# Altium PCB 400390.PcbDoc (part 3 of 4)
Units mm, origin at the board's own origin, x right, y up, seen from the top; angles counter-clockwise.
Board outline 50.8 x 50.4 mm, 4 copper layers (Top Layer, Mid Layer 1, Mid Layer 2, Bottom Layer), stack 1.507 mm thick; 236 components, 197 nets, 1131 pads, 994 vias.
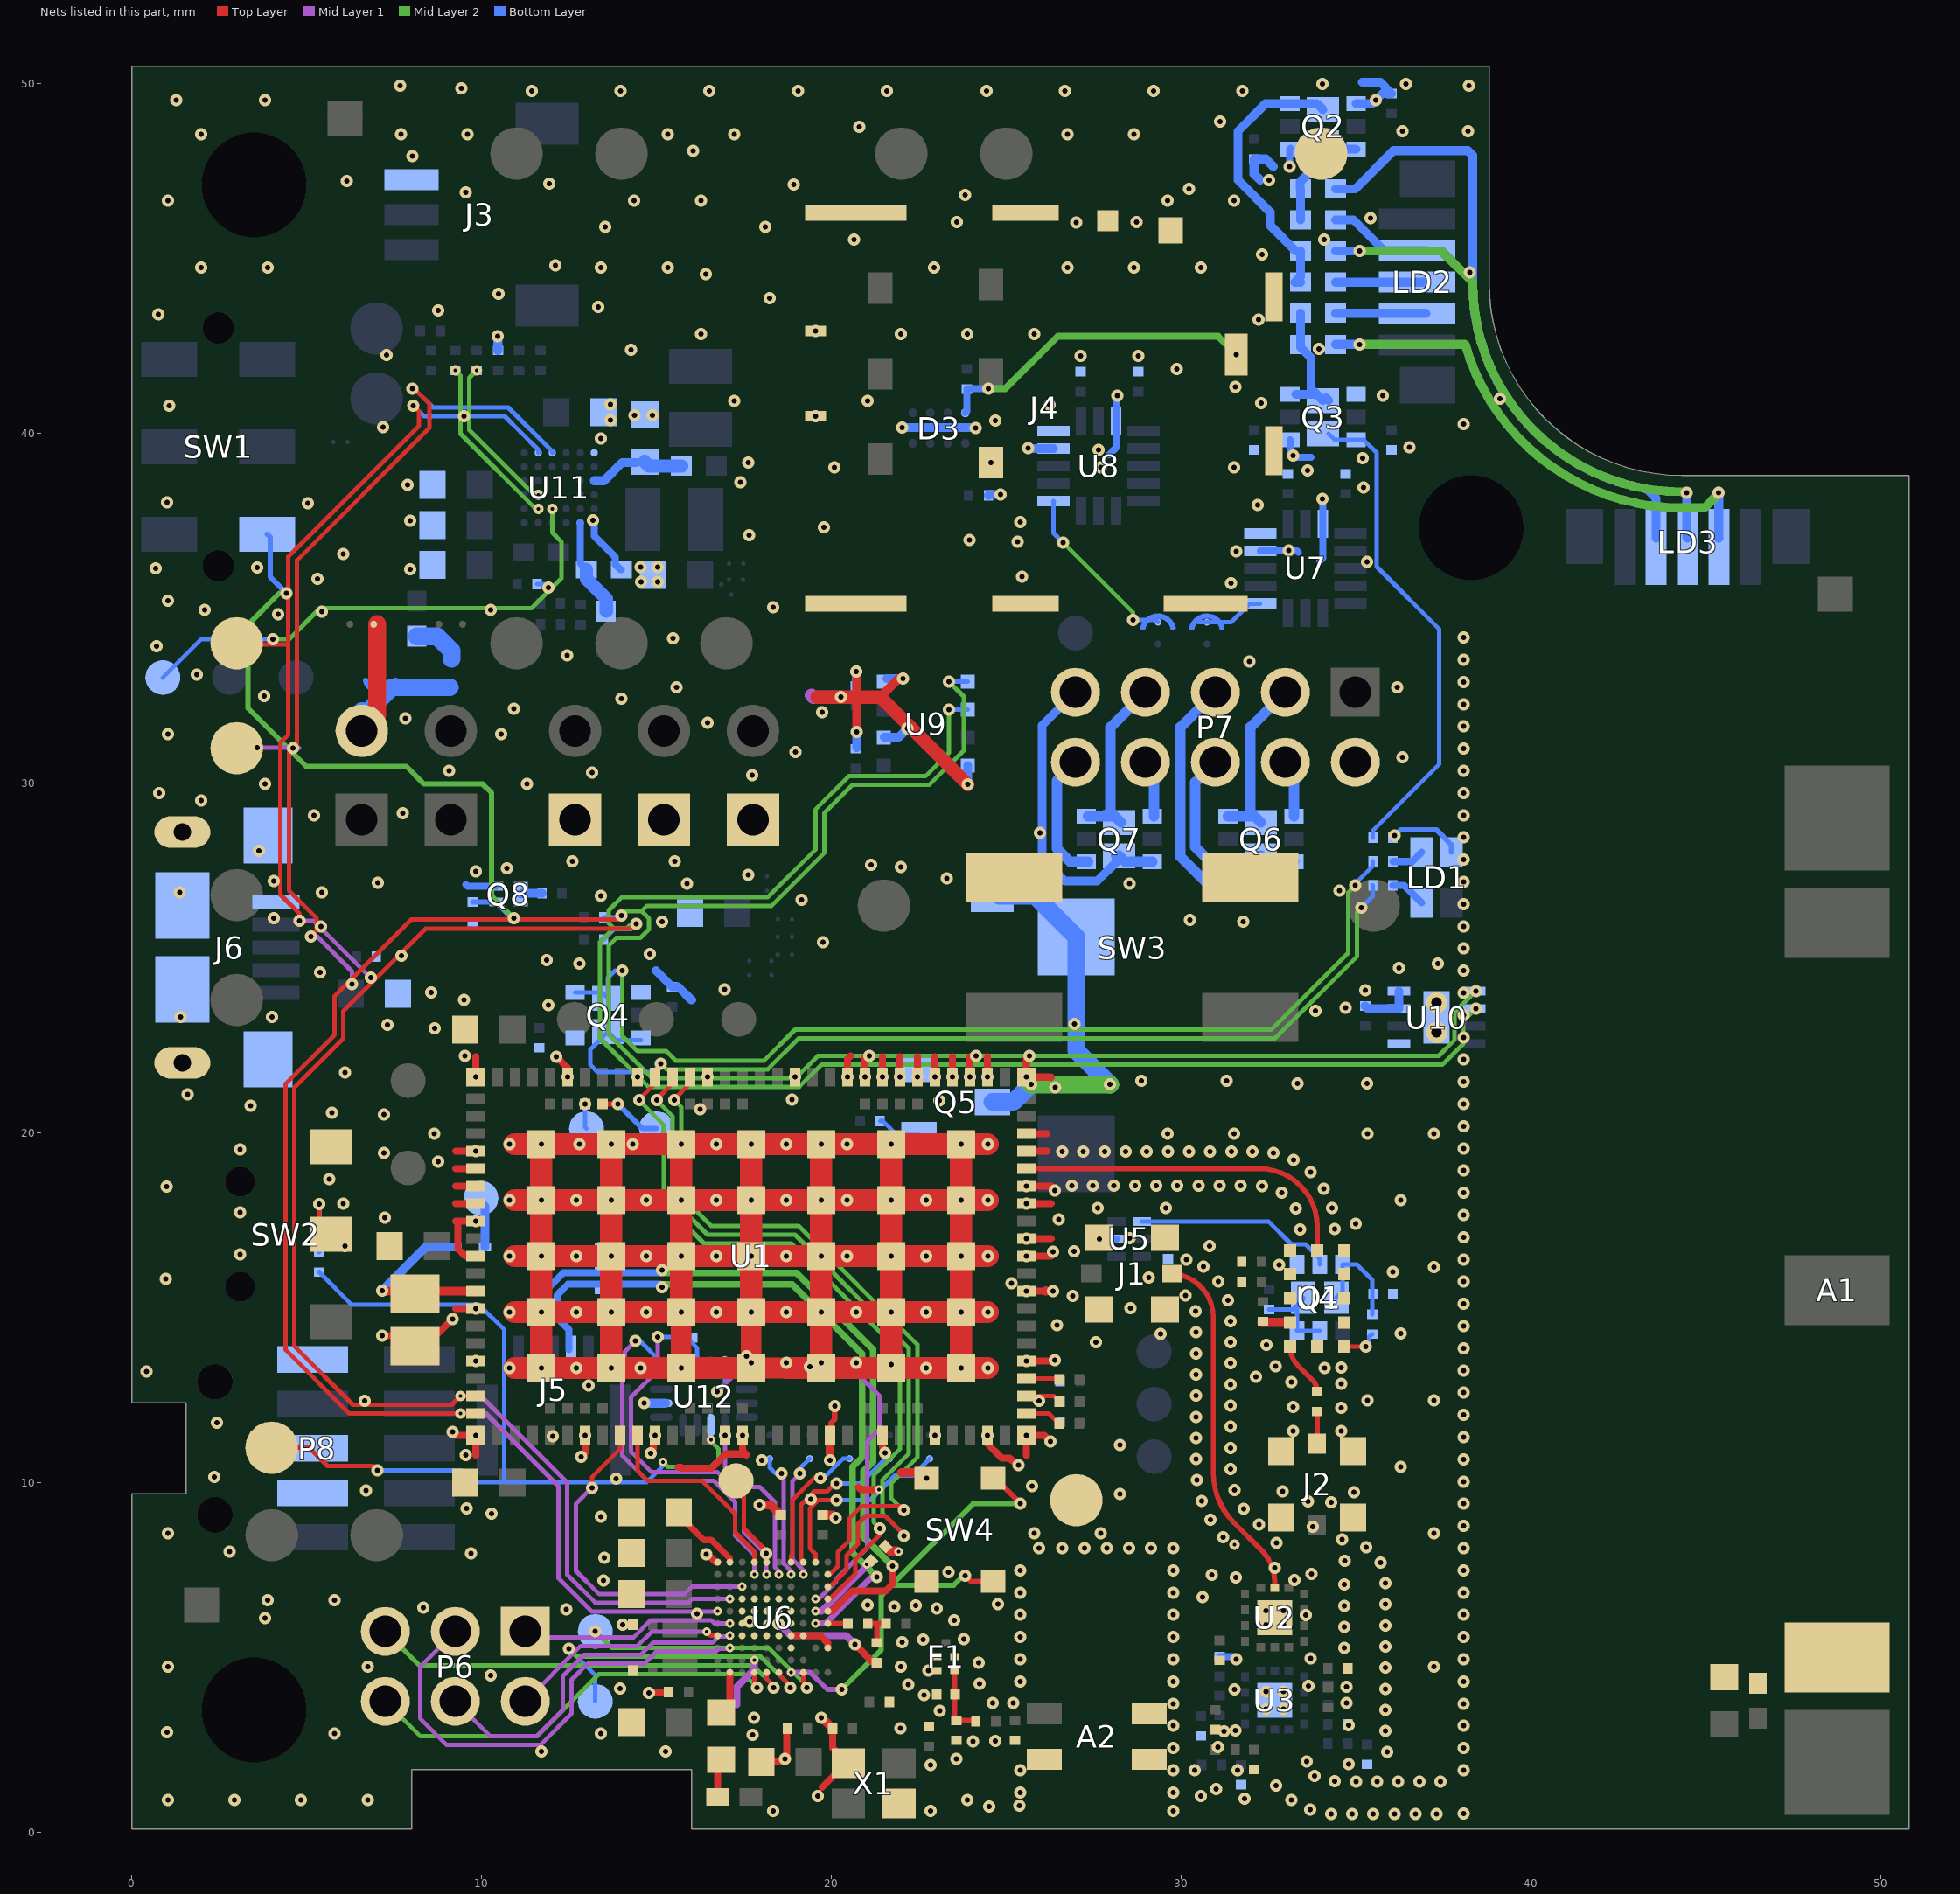
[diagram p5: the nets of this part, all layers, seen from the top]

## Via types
v1: diameter 0.35, hole 0.15, Top Layer to Bottom Layer, tented both sides, 565 vias
v2: diameter 0.35, hole 0.15, Top Layer to Mid Layer 1, tented both sides, 201 vias
v3: diameter 0.35, hole 0.15, Mid Layer 2 to Bottom Layer, tented both sides, 153 vias
v4: diameter 0.25, hole 0.1, Top Layer to Mid Layer 1, tented both sides, 35 vias
v5: diameter 0.3, hole 0.1, Mid Layer 2 to Bottom Layer, tented both sides, 26 vias
v6: diameter 0.25, hole 0.1, Mid Layer 2 to Bottom Layer, tented both sides, 5 vias
v7: diameter 0.35, hole 0.15, Top Layer to Mid Layer 1, 4 vias
v8: diameter 0.3, hole 0.1, Top Layer to Mid Layer 1, tented both sides, 3 vias
v9: diameter 0.61, hole 0.305, Top Layer to Bottom Layer, tented both sides, 2 vias

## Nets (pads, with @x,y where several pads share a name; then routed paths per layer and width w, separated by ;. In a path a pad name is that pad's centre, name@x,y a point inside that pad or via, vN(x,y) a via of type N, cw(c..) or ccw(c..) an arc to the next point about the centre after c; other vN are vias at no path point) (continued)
GND: A2.2 C1.1 C2.1 C3.2 C4.2 C5.1 C6.1 C7.1 C8.1 C12.1 C13.1 C14.1 C16.1 C17.1 C18.2 C19.2 C20.1 C21.2 C22.2 C23.2 C24.2 C25.2 C26.2 C27.2 C28.1 C29.2 C30.2 C31.2 C32.2 C33.2 C35.2 C36.1 C37.1 C38.1 C39.1 C40.1 C41.1 C42.1 C43.2 C44.2 C45.1 C46.1 C47.1 C48.1 C49.1 C50.1 C51.1 C53.1 C54.2 C55.2 C56.2 C57.1 CR1.1 D3.B1 D3.B2 F1.2 F1.3 F1.5 J1.2 J2.2 J3.1 J4.0 J4.C5 J4.CSW J6.5 J6.6@1.45,22 J6.6@1.45,24.1 J6.6@1.45,26.5 J6.6@1.45,28.6 J6.6@3.9,22.1 J6.6@3.9,28.5 L4.1 L5.1 L6.1 L7.1 L15.2 P3.1 P4.1 P5.1 P7.2 P8.3 P8.5 P8.9 Q1.1 Q2.1 Q2.4 Q3.1 Q3.4 Q4.1 Q4.4 Q5.2 Q8.2 R4.1 R5.1 R6.1 R32.1 R40.2 R41.1 R42.1 R43.1 R44.1 R45.1 R46.1 R48.2 ST11.2 SW2.1 SW3.1 SW4.1 TP15.1 TP16.1 U1.1 U1.5 U1.6 U1.7 U1.8 U1.9 U1.11 U1.14 U1.17 U1.21 U1.27 U1.31 U1.36 U1.41 U1.44 U1.47 U1.50 U1.52 U1.56 U1.60 U1.62 U1.63 U1.65 U1.66 U1.68 U1.69 U1.72 U1.74 U1.75 U1.76 U1.77 U1.78 U1.79 U1.80 U1.81 U1.82 U1.85 U1.90 U1.94 U1.98 U1.103 U2.15 U3.15 U4.2 U4.4 U4.5 U4.6 U4.7 U4.9 U4.10 U4.11 U5.2 U6.B7 U6.C1 U6.C4 U6.D3 U6.D4 U6.D5 U6.D6 U6.D7 U6.D8 U6.E4 U6.E5 U6.E6 U6.E7 U6.E8 U6.F4 U6.F5 U6.F6 U6.F7 U6.F8 U6.G4 U6.G5 U6.G6 U6.G7 U6.G8 U6.K10 U7.12 U7.13 U7.16 U8.12 U8.13 U8.16 U9.1 U9.5 U9.7 U10.1 U10.3 U10.4 U10.9 U11.A1 U11.F1 U12.6 X1.2 X1.4 | length 187.5
  Top Layer w0.152: U1.41@19.956,11.357 19.98,11.381 19.98,11.701 20.091,11.812 v1(20.091,12.192)
  Top Layer w0.2: v1(7.163,14.199) C3.2@7.744,14.199 ; C3.2@8.522,14.034 v1(9.169,14.681) ; v2@9.255,11.357 v2(9.836,11.357) 9.836,10.776 ; 9.255,14.977 v2(9.836,14.977) ; 9.255,17.977 U1.8@9.836,17.977 ; 9.255,18.477 U1.7@9.836,18.477 ; 9.255,18.977 U1.6@9.836,18.977 ; 9.255,19.477 v2(9.836,19.477) ; U1.11@9.836,16.477 9.533,16.477 9.327,16.683 9.327,17.405 9.255,17.477 v2(9.836,17.477) ; v2(9.836,21.597) 9.836,22.178 ; v1(12.141,22.174) 12.456,21.859 v2(12.456,21.597) ; v1(12.852,10.744) 12.956,10.848 v2(12.956,11.357) ; v1@14.732,3.988 15.315,3.988 C21.2@15.345,4.017 ; C28.1@17.927,1.985 C28.1@18.054,1.858 ; C28.1@18.003,2.011 18.038,2.046 18.561,2.046 18.729,2.214 C29.2@18.729,2.975 ; U6.D4@18.847,5.626 19.635,5.626 19.638,5.622 19.692,5.622 19.897,5.417 U6.C1@19.897,5.276 ; 19.736,1.295 19.739,1.295 20.091,1.647 20.159,1.647 X1.2@20.484,1.972 20.434,1.972 20.109,2.297 20.109,2.347 20.035,2.421 C19.2@20.035,2.97 ; v2(20.456,21.597) 20.456,22.11 20.549,22.203 ; v1(20.669,5.382) 21.198,4.853 C20.1@21.301,4.853 ; v2(20.956,21.597) v7@20.956,22.178 ; v2(21.456,21.597) 21.456,22.178 ; v2(21.956,21.597) 21.956,22.178 ; v2(22.456,21.597) 22.456,22.178 ; v2(22.956,21.597) 22.956,22.178 ; v2(23.456,21.597) 23.456,22.178 ; v2(23.956,21.597) 23.956,22.178 ; v2(24.456,11.357) 24.456,11.119 24.581,10.994 24.713,10.862 24.875,10.7 25.1,10.7 25.175,10.625 ; v2(24.456,21.597) 24.456,22.178 ; 25.576,10.776 v2(25.576,11.357) 26.083,11.357 v1(26.264,11.176) ; U1.68@25.576,19.477 26.157,19.477 ; U1.69@25.576,19.977 26.157,19.977 ; v2(25.576,21.597) v7@25.576,22.178
  Top Layer w0.203: v1(14.834,10.846) 14.834,10.886 14.908,10.96 14.908,11.309 v2(14.956,11.357) ; 15.621,10.439 15.698,10.439 15.719,10.419 16.572,10.419 16.974,10.82 17.551,10.82 ; v1@16.417,8.005 16.696,7.726 U6.K10@16.747,7.726 ; U1.36@17.456,11.357 v2(17.458,11.355) 17.458,10.914 17.551,10.82 ; 17.577,10.795 17.551,10.82 ; 20.774,9.881 20.85,9.804 v4(21.361,9.804) ; 21.456,11.008 U1.44@21.456,11.357 ; v2(25.576,13.477) v1@26.28,13.477 ; v2(25.576,15.477) 26.13,15.477 v2@26.28,15.477 ; v2(25.576,16.477) v2@26.28,16.477 ; v2(25.576,16.977) 26.28,16.977 ; v2(25.576,17.977) 26.28,17.977 ; v2(25.576,18.477) v2@26.28,18.477 ; v2(25.576,21.597) 26.28,21.597
  Top Layer w0.254: v2(9.169,11.455) v2@9.188,11.437 ; v1(17.949,9.367) 18.261,9.367 C23.2@18.55,9.078 ; v1(19.71,3.277) 19.728,3.277 C19.2@20.035,2.97 ; C24.2@19.745,9.078 20.031,9.078 v1(20.117,8.992) ; 19.956,10.837 U1.41@19.956,11.357 ; v1(20.727,31.465) 20.727,32.309 ; 20.727,32.461 v1@20.727,33.242 ; 21.394,32.461 21.903,32.97 22.03,32.97 v1(22.048,32.988) ; C25.2@21.558,8.175 C25.2@21.547,8.175 21.675,8.047 v4@21.855,8.047 ; 21.996,10.287 22.565,10.287 v2(22.723,10.129) ; 26.13,15.477 26.139,15.486
  Top Layer w0.381: 19.583,32.461 v1(20.269,32.461) 20.727,32.461 21.394,32.461 v1(23.895,29.96)
  Top Layer w0.508: v2(13.706,19.677) U1.103@13.824,19.677 ; v2(15.706,19.677) U1.103@15.706,19.712
  Top Layer w0.584: v2(15.706,13.277) v2(15.706,14.877) ; U1.103@17.706,13.277 v2(17.706,14.877)
  Top Layer w0.597: U1.103@17.706,13.277 v2@18.706,13.277
  Top Layer w0.635: v2@10.944,13.277 v2(11.706,13.277) ; v1@10.944,14.877 v2(11.706,14.877) ; v1@10.944,16.477 v2(11.706,16.477) ; v1@10.944,18.077 v2(11.706,18.077) ; v1@10.944,19.677 v2(11.706,19.677) ; U1.103@17.706,13.277 v2(15.706,13.277) v2(13.706,13.277) ; v2@18.706,13.277 U1.103@19.706,13.277 ; v1(24.468,13.277) v2(23.706,13.277) ; v2(24.468,14.877) v2(23.706,14.877) ; v2(24.468,16.477) v2(23.706,16.477) ; v1(24.468,18.077) v2(23.706,18.077) ; v1(24.468,19.677) v2(23.706,19.677) ; v2(11.706,13.277) v2(12.706,13.277) v2(13.706,13.277) ; v2(11.706,13.277) v2(11.706,14.877) ; v2(11.706,14.877) v1(12.706,14.877) v2(13.706,14.877) ; v2(11.706,14.877) v2(11.706,16.477) ; v2(11.706,16.477) v1(12.706,16.477) v2(13.706,16.477) ; v2(11.706,16.477) v2(11.706,18.077) ; v2(11.706,18.077) v1(12.706,18.077) v2(13.706,18.077) ; v2(11.706,18.077) v2(11.706,19.677) ; v2(11.706,19.677) v2(13.706,19.677) ; v2(13.706,13.277) v2(13.706,14.877) ; v2(13.706,14.877) v1(14.706,14.877) v2(15.706,14.877) ; v2(13.706,14.877) v2(13.706,16.477) ; v2(13.706,16.477) v1(14.706,16.477) v2(15.706,16.477) ; v2(13.706,16.477) v2(13.706,18.077) ; v2(13.706,18.077) v1(14.706,18.077) v2(15.706,18.077) ; v2(13.706,18.077) v2(13.706,19.677) ; v2(13.706,19.677) v2(15.706,19.677) ; v2(15.706,14.877) v1(16.706,14.877) v2(17.706,14.877) ; v2(15.706,14.877) v2(15.706,16.477) ; v2(15.706,16.477) v1(16.706,16.477) v2(17.706,16.477) ; v2(15.706,16.477) v2(15.706,18.077) ; v2(15.706,18.077) v1(16.706,18.077) v2(17.706,18.077) ; v2(15.706,18.077) v2(15.706,19.677) ; v2(15.706,19.677) v1(16.706,19.677) v2(17.706,19.677) ; v2(17.706,14.877) v1(18.706,14.877) v2(19.706,14.877) ; v2(17.706,14.877) v2(17.706,16.477) ; v2(17.706,16.477) v1(18.706,16.477) v2(19.706,16.477) ; v2(17.706,16.477) v2(17.706,18.077) ; v2(17.706,18.077) v1(18.706,18.077) v2(19.706,18.077) ; v2(17.706,18.077) v2(17.706,19.677) ; v2(17.706,19.677) v2(18.706,19.677) v2(19.706,19.677) ; U1.103@19.706,13.277 U1.103@21.706,13.277 ; U1.103@19.706,13.277 v2(19.706,14.877) ; v2(19.706,14.877) v2(20.706,14.877) v2(21.706,14.877) ; v2(19.706,14.877) v2(19.706,16.477) ; v2(19.706,16.477) v1(20.452,16.477) v2(21.706,16.477) ; v2(19.706,16.477) v2(19.706,18.077) ; v2(19.706,18.077) v1(20.452,18.077) v2(21.706,18.077) ; v2(19.706,18.077) v2(19.706,19.677) ; v2(19.706,19.677) v1(20.452,19.677) v2(21.706,19.677) ; U1.103@21.706,13.277 v2(22.706,13.277) v2(23.706,13.277) ; U1.103@21.706,13.277 v2(21.706,14.877) ; v2(21.706,14.877) v2(22.706,14.877) v2(23.706,14.877) ; v2(21.706,14.877) v2(21.706,16.477) ; v2(21.706,16.477) v2(22.706,16.477) v2(23.706,16.477) ; v2(21.706,16.477) v2(21.706,18.077) ; v2(21.706,18.077) v1(22.706,18.077) v2(23.706,18.077) ; v2(21.706,18.077) v2(21.706,19.677) ; v2(21.706,19.677) v2(23.706,19.677) ; v2(23.706,13.277) v2(23.706,14.877) ; v2(23.706,14.877) v2(23.706,16.477) ; v2(23.706,16.477) v2(23.706,18.077) ; v2(23.706,18.077) v2(23.706,19.677)
  Mid Layer 1 w0.2: 17.297,3.658 17.297,4.166 17.797,4.665 v4(17.797,4.926) ; v1(18.491,5.969) 18.834,5.626 20.422,5.626 v1@20.572,5.476
  Mid Layer 1 w0.381: 19.431,32.512 19.482,32.461 v1(20.269,32.461)
  Bottom Layer w0.2: 9.55,27.1 9.603,27.047 Q8.2@10.42,27.047 ; 27.94,39.395 28.135,39.591 v3@28.135,41.097 ; U7.12@32.266,36.644 33.307,36.644 33.35,36.601 ; v1(33.096,47.625) 33.096,48.133 Q2.1@33.122,48.158 ; Q3.1@33.106,39.812 33.106,39.487 33.274,39.319 33.706,39.319 ; 33.96,36.347 34.053,36.441 v3@34.053,38.1
  Bottom Layer w0.203: U11.F1@13.221,37.446 13.221,37.065 13.825,36.46 13.825,36.249 13.968,36.106 C47.1@14.001,36.106 ; v3(27.661,16.967) U5.2@28.151,16.967 ; C17.1@31.096,5.032 31.497,5.032 v1(31.579,4.95)
  Bottom Layer w0.254: v1(10.465,42.774) 10.468,42.77 R32.1@10.468,42.369 ; v1@14.78,12.271 U12.6@15.26,12.271 ; 14.986,24.638 R45.1@15.448,24.176 15.625,24.176 16.002,23.799 ; C40.1@20.708,32.793 v1@20.708,33.242 ; C41.1@20.727,31.012 v1(20.727,31.465) ; U9.7@21.512,31.312 21.921,31.312 v1(22.175,31.566) ; U9.5@21.588,32.988 v1(22.048,32.988) ; v3(22.028,40.165) 24.116,40.165 v3(24.128,40.152) ; v1(23.895,29.96) U9.1@23.895,30.495 ; C54.2@24.491,38.227 24.517,38.252 v3(24.841,38.252) ; v3(25.629,39.573) 25.637,39.565 U8.12@26.348,39.565 ; 32.258,47.244 32.08,47.422 R42.1@32.08,47.848 32.416,47.848 32.639,47.625 ; Q2.4@34.996,49.431 35.461,49.431 v1(35.56,49.53) 35.746,49.716 R41.1@36.012,49.716 35.69,50.038 35.179,50.038 ; C42.1@35.255,23.628 35.333,23.55 U10.3@36.225,23.55 U10.4@36.225,24.05
  other v1: 34.28,0.532 34.884,0.53 35.488,0.53 36.092,0.53 36.696,0.53 37.3,0.53 38.075,0.536 18.339,0.61 22.835,0.61 29.775,0.612 33.688,0.651 24.511,0.737 25.375,0.759 1.031,0.927 2.936,0.927 4.841,0.927 6.746,0.927 23.891,0.927 33.148,0.923 19.609,1.041 25.4,1.143 29.775,1.143 32.71,1.338 34.39,1.461 34.994,1.458 35.598,1.458 36.202,1.458 36.806,1.458 37.41,1.458 33.807,1.62 25.4,1.778 29.775,1.778 38.075,1.778 22.835,1.93 34.789,1.949 33.585,2.03 18.669,2.108 23.574,2.108 15.265,2.311 35.883,2.297 29.775,2.413 38.075,2.413 24.05,2.6 24.691,2.616 17.753,2.788 5.793,2.832 13.413,2.832 1.016,2.87 35.835,2.899 21.971,2.972 29.775,3.048 38.075,3.048 17.789,3.281 23.1,3.475 35.835,3.503 32.421,3.531 32.921,3.531 29.775,3.683 38.075,3.683 24.615,3.708 25.199,3.708 22.65,3.925 14.783,3.988 32.421,4.031 32.921,4.031 13.964,4.115 35.835,4.107 22.197,4.226 24.232,4.253 25.4,4.318 29.775,4.318 38.075,4.318 22.775,4.625 35.835,4.711 1.031,4.737 6.746,4.737 21.986,4.737 37.226,4.737 24.211,4.856 25.4,4.953 29.775,4.953 38.075,4.953 33.692,4.974 34.662,5.275 35.835,5.315 22.02,5.438 22.62,5.509 23.788,5.524 25.4,5.588 29.775,5.588 38.075,5.588 34.662,5.879 14.041,5.944 32.421,5.944 32.921,5.944 35.835,5.919 17.655,6.023 23.515,6.063 3.81,6.121 25.4,6.223 29.775,6.223 38.075,6.223 32.421,6.344 32.921,6.344 12.421,6.375 23.013,6.399 8.331,6.426 21.801,6.453 21.031,6.502 22.415,6.485 34.662,6.483 24.765,6.528 35.835,6.523 3.888,6.642 5.793,6.642 25.4,6.858 29.775,6.858 38.075,6.858 34.662,7.087 35.835,7.127 13.489,7.199 30.868,7.363 33.728,7.389 23.343,7.442 25.4,7.493 29.775,7.493 38.075,7.493 35.692,7.714 16.417,7.955 2.794,8.026 25.94,8.128 26.6,8.128 27.235,8.128 27.87,8.128 28.505,8.128 29.14,8.128 29.775,8.128 38.075,8.128 35.279,8.155 34.601,8.379 31.193,8.444 1.031,8.547 25.796,8.547 27.701,8.547 37.226,8.547 38.075,8.763 30.839,8.934 13.413,9.028 10.287,9.12 31.791,9.257 38.075,9.398 34.286,9.442 33.622,9.469 30.585,9.482 28.245,9.677 6.7,9.775 31.519,9.796 25.73,9.906 38.075,10.033 30.453,10.071 2.362,10.16 31.408,10.39 36.273,10.452 25.35,10.5 38.075,10.668 30.425,10.674 9.55,10.795 31.407,10.994 28.245,11.074 30.425,11.278 38.075,11.303 33.202,11.478 34.574,11.478 31.407,11.598 2.438,11.709 38.075,11.938 34.574,12.138 33.202,12.163 14.653,12.271 35.321,12.357 37.226,12.357 38.075,12.573 34.574,12.824 33.15,12.875 32.131,13.03 30.425,13.09 0.425,13.175 38.075,13.208 14.554,13.277 34.1,13.275 34.574,13.284 32.694,13.327 31.407,13.41 26.389,13.502 30.425,13.694 38.075,13.843 32.436,13.945 27.559,14.021 31.407,14.014 36.273,14.262 30.425,14.298 38.075,14.478 26.441,14.503 31.407,14.618 10.792,14.877 30.404,14.902 38.075,15.113 31.339,15.218 30.125,15.35 38.075,15.748 31.066,15.757 0.975,15.825 29.07,15.87 36.043,16.027 30.631,16.176 37.226,16.167 38.075,16.383 10.792,16.477 3.1,16.525 30.81,16.764 38.075,17.018 34.98,17.399 7.239,17.577 38.075,17.653 3.1,17.725 27.61,17.856 29.566,17.856 6.05,17.975 10.792,18.077 36.273,18.072 38.075,18.288 1,18.466 5.65,18.675 38.075,18.923 8.763,19.177 7.214,19.431 3.1,19.525 38.075,19.558 10.792,19.677 14.325,19.677 8.651,19.977 29.606,19.977 31.511,19.977 35.321,19.977 37.226,19.977 38.075,20.193 7.214,20.523 5.725,20.575 3.4,20.775 38.075,20.828 23.089,20.93 1.6,21.1 33.325,21.412 35.306,21.412 38.075,21.463 28.854,21.488 31.293,21.488 6.1,21.725 9.525,22.2 8.661,22.987 7.315,23.089 4.013,23.317 34.696,23.571 9.5,23.8 16.942,24.105 37.338,24.841 15.164,26.035 31.775,26.035 30.251,26.086 19.152,26.67 5.436,26.873 28.524,27.127 7.036,27.153 23.292,27.28 17.628,27.381 9.83,27.483 10.719,27.559 21.986,27.597 21.133,27.661 12.598,27.762 15.519,27.762 38.075,29.083 1.983,29.502 0.787,29.718 38.075,29.718 3.81,29.972 11.303,29.972 17.729,30.226 13.157,30.302 9.068,30.353 38.075,30.353 38.075,30.988 1.031,31.407 10.556,31.407 38.075,31.623 16.459,31.725 38.075,32.258 13.995,32.41 3.785,32.487 15.57,32.741 36.17,32.741 38.075,32.893 1.854,33.096 20.708,33.191 31.953,33.477 38.075,33.528 0.711,33.909 38.075,34.163 2.083,34.95 1.031,35.217 31.42,35.712 14.554,35.75 15.037,35.75 7.964,36.109 0.686,36.144 3.581,36.17 14.553,36.182 15.037,36.182 31.572,36.627 33.071,36.652 23.952,36.957 19.787,37.313 7.964,37.506 32.182,37.948 1.016,38.024 35.204,38.456 7.888,38.522 24.564,39.168 35.179,39.294 36.525,39.599 13.411,39.853 38.075,40.259 13.689,40.375 14.376,40.513 14.884,40.513 19.544,40.488 1.067,40.792 13.689,40.832 17.223,40.932 35.763,41.072 16.271,42.837 19.544,42.928 0.762,43.409 8.763,43.51 18.237,43.866 10.49,43.993 16.408,44.552 1.983,44.742 3.888,44.742 13.413,44.742 15.318,44.742 28.653,44.742 30.558,44.742 12.116,44.806 32.309,45.11 20.65,45.542 13.538,45.898 18.11,45.898 23.582,46.041 27,46.03 28.723,46.041 1.031,46.647 14.366,46.647 16.271,46.647 29.606,46.647 31.511,46.647 23.825,46.812 9.55,46.888 30.226,46.99 18.923,47.117 6.147,47.219 32.512,47.244 8.026,47.93 16.053,48.082 1.983,48.552 7.698,48.552 9.603,48.552 15.318,48.552 17.223,48.552 26.748,48.552 28.653,48.552 36.322,48.641 38.202,48.641 20.803,48.768 31.115,48.92 1.27,49.53 3.81,49.53 11.43,49.784 13.97,49.784 16.51,49.784 19.05,49.784 21.59,49.784 24.43,49.784 26.67,49.784 29.21,49.784 31.75,49.784 9.423,49.86 7.671,49.936 38.227,49.936 34.036,49.987 36.424,49.987
  other v2: 30.995,1.241 30.385,1.775 31.604,1.775 31.553,2.918 34.779,3.07 31.528,4.089 34.728,4.162 33.636,4.188 10.262,4.496 30.614,6.728 31.559,7.287 34.678,7.769 13.513,7.849 32.725,8.275 32.225,8.8 9.576,9.271 34.929,9.728 32.897,9.754 13.843,10.109 18.009,10.643 19.964,10.643 21.532,10.849 22.956,11.357 30.425,11.882 31.407,12.202 30.425,12.486 31.407,12.806 10.792,13.277 21.706,13.379 17.706,13.429 18.706,13.429 19.706,13.429 20.706,13.429 9.836,13.477 29.413,14.249 28.55,14.986 26.899,15.342 26.338,15.477 26.338,16.604 26.933,16.612 28.524,16.993 33.397,17.243 34.379,17.25 26.492,17.526 33.273,17.835 34.308,17.85 32.878,18.292 26.389,18.35 34.077,18.408 26.868,18.486 27.472,18.486 28.076,18.486 28.68,18.486 29.284,18.486 29.888,18.486 30.492,18.486 31.096,18.486 31.7,18.486 32.304,18.48 33.703,18.882 33.207,19.226 32.637,19.427 26.598,19.468 27.202,19.468 27.806,19.468 28.41,19.468 29.014,19.468 29.618,19.468 30.222,19.468 30.826,19.468 31.43,19.468 32.034,19.468 12.8,19.677 26.393,21.303 14.456,21.597 16.456,21.597 18.956,21.597 38.075,22.098 38.075,22.733 26.949,23.114 1.397,23.317 38.075,23.368 33.833,23.495 38.075,24.003 38.075,24.638 38.075,25.273 19.761,25.451 38.075,25.908 4.064,26.137 38.075,26.543 1.372,26.873 34.528,26.924 38.075,27.178 38.075,27.813 3.632,28.067 38.075,28.448 36.095,28.5 25.959,28.575 5.207,29.083 7.747,29.134 36.322,30.734 18.974,30.886 19.736,32.029 12.446,33.655 15.469,34.138 5.436,34.9 10.262,34.95 18.339,35.027 25.451,35.898 6.045,36.551 13.183,37.516 5.029,37.998 17.399,38.608 7.188,40.183 9.5,40.488 32.283,40.869 39.116,40.996 7.29,42.24 33.934,42.418 38.252,44.602 34.087,45.542 35.408,46.152
  other v3: 31.807,0.962 30.563,1.038 11.709,2.311 31.045,2.435 31.223,2.892 34.728,3.705 33.56,6.22 16.154,6.248 33.23,7.21 32.671,7.566 9.703,7.976 18.136,7.976 33.761,8.734 19.406,9.525 12.04,11.328 6.655,12.344 25.933,12.344 13.056,12.776 19.39,13.31 17.577,13.614 25.146,15.697 32.791,16.231 30.15,16.383 6.099,16.764 16.25,20.675 18.872,20.955 11.913,23.647 8.564,24.016 35.255,24.079 5.385,24.587 36.22,24.714 12.802,24.841 11.862,24.943 7.714,25.07 14.808,25.121 5.41,25.908 13.411,26.772 15.875,27.127 4.062,27.203 7.823,31.852 10.922,32.131 4.191,34.823 5.309,35.839 25.324,36.906 17.653,37.084 25.4,37.465 34.036,38.125 33.604,38.938 20.081,39.027 27.701,39.027 31.511,39.027 17.628,39.167 33.198,39.37 27.635,39.522 24.689,40.361 26.238,40.818 21.033,40.932 28.169,41.072 31.547,41.326 29.87,41.834 27.127,42.215 28.778,42.215 14.275,42.393 21.986,42.837 23.891,42.837 25.796,42.837 32.207,43.256 13.335,43.612 22.938,44.742 26.748,44.742 11.938,47.142
  other v4: 21.92,8.026
  other v7: 21.082,22.203 24.13,22.203 25.654,22.203 35.306,36.322
  other v8: 31.525,8.225
  other v9: 37.3,22.875 37.3,23.725
GPS_EN: C7.2 Q1.3 R7.2 | length 3
  Bottom Layer w0.125: Q1.3@34.435,15.291 34.61,15.466 Q1.3@34.61,16.236 35.021,16.236 35.458,15.799 R7.2@35.458,14.814
GPS_LNA: J2.1 L1.2 | length 0.9
  Top Layer w0.146: J2.1@33.888,11.114 L1.2@33.888,12.034
GPS_LNA_IN: L1.1 U4.1 | length 1.6
  Top Layer w0.146: U4.1@33.113,13.89 ccw(c33.889,13.89) 33.34,13.342 33.754,12.928 cw(c33.429,12.604) L1.1@33.888,12.604
GPS_RF: U1.67 U4.8 | length 9.9
  Top Layer w0.146: U1.67@25.576,18.977 32.234,18.977 cw(c32.234,17.323) 33.888,17.323 U4.8@33.888,16.64
ICS: R37.1 U11.E5 | length 5
  Mid Layer 2 w0.125: v5(9.249,41.799) 9.398,41.65 9.398,39.991 11.543,37.846 v5(11.621,37.846)
ILIM: R36.1 U11.D5 | length 4.6
  Mid Layer 2 w0.125: v5(9.858,41.799) 9.648,41.588 9.648,40.095 11.497,38.246 v5(11.621,38.246) ; v5@9.909,41.748 v5@9.96,41.799
LTE_RF: J1.3 U2.13 | length 10.3
  Top Layer w0.146: J1.3@29.676,15.977 cw(c29.676,14.737) 30.916,14.737 30.916,10.288 ccw(c32.944,10.288) 31.51,8.854 32.29,8.074 cw(c31.37,7.154) 32.671,7.154 U2.13@32.671,6.989
LW_BLUE: Q3.3 R17.1 R20.1 | length 3.5
  Bottom Layer w0.254: Q3.3@33.269,41.112 Q3.3@33.876,41.112 ; R17.1@33.409,43.434 R20.1@33.409,42.545 33.409,42.461 33.711,42.159 33.711,41.278 Q3.3@33.876,41.112 ; Q3.3@34.051,40.937 Q3.3@33.876,41.112 ; Q3.3@34.132,41.019 Q3.3@34.214,40.937
LW_GREEN: Q2.6 R16.1 R19.1 | length 3.1
  Bottom Layer w0.254: R16.1@33.409,46.101 R19.1@33.409,46.99 33.401,46.998 33.401,47.193 34.339,48.131 Q2.6@34.996,48.131
LW_RED: Q2.3 R15.1 R18.1 | length 8.2
  Bottom Layer w0.254: R15.1@33.409,44.323 33.249,44.323 33.409,44.483 R18.1@33.409,45.212 33.274,45.212 32.543,45.943 32.543,46.324 31.623,47.244 31.623,48.641 32.413,49.431 Q2.3@33.106,49.431 33.876,49.431 Q2.3@34.051,49.256
M\R\: R34.2 TP24.1 U11.E4 | length 15
  Mid Layer 2 w0.125: v3(4.039,34.112) 4.496,34.112 5.385,35.001 11.43,35.001 12.283,35.854 12.283,36.903 12.021,37.165 v5(12.021,37.846)
  Bottom Layer w0.125: TP24.1@0.889,33.02 1.981,34.112 v3(4.039,34.112) ; R34.2@11.588,35.687 11.811,35.687 v3(11.913,35.585)
MOS_1_D: P7.3 Q6.6 | length 5
  Bottom Layer w0.3: Q6.6@31.33,29.05 31.975,29.05 Q6.6@32.1,29.05 ; Q6.6@32.275,28.875 Q6.6@32.1,29.05 ; P7.3@32.975,32.6 31.975,31.6 31.975,29.175 Q6.6@32.1,29.05
MOS_1_S: P7.4 Q6.1 | length 1.7
  Bottom Layer w0.3: P7.4@32.975,30.6 33.22,30.355 Q6.1@33.22,29.05
MOS_2_D: P7.5 Q6.3 | length 9.1
  Bottom Layer w0.3: P7.5@30.975,32.6 29.975,31.6 29.975,27.9 30.675,27.2 31.675,27.2 32.275,27.8 Q6.3@32.275,27.925 32.45,27.75 Q6.3@33.22,27.75
MOS_2_S: P7.6 Q6.4 | length 3.8
  Bottom Layer w0.3: P7.6@30.975,30.6 30.4,30.025 30.4,28.175 30.825,27.75 Q6.4@31.33,27.75
MOS_3_D: P7.7 Q7.6 | length 5
  Bottom Layer w0.3: Q7.6@27.33,29.05 27.975,29.05 Q7.6@28.1,29.05 ; Q7.6@28.275,28.875 Q7.6@28.1,29.05 ; P7.7@28.975,32.6 27.975,31.6 27.975,29.175 Q7.6@28.1,29.05
MOS_3_S: P7.8 Q7.1 | length 1.7
  Bottom Layer w0.3: P7.8@28.975,30.6 29.22,30.355 Q7.1@29.22,29.05
MOS_4_D: P7.9 Q7.3 | length 9.1
  Bottom Layer w0.249: 26.025,31.65 P7.9@26.975,32.6 ; 26.026,31.649 26.026,27.849 26.675,27.2 27.601,27.2 28.13,27.729 Q7.3@28.13,27.864
  Bottom Layer w0.27: Q7.3@28.12,27.925 Q7.3@28.225,27.925
  Bottom Layer w0.3: Q7.3@28.225,27.8 Q7.3@28.225,27.925 28.4,27.75 Q7.3@29.17,27.75
MOS_4_S: P7.10 Q7.4 | length 3.7
  Bottom Layer w0.3: P7.10@26.975,30.6 26.441,30.066 26.441,28.134 26.825,27.75 Q7.4@27.28,27.75 Q7.4@27.33,27.75
NetA1_2: A1.2 C15.2 L8.2
NetBz1_2: Bz1.2 D2.2 Q5.3 | length 10.9
  Mid Layer 2 w0.508: v3(25.705,21.387) v3(27.965,21.387)
  Bottom Layer w0.508: Q5.3@24.604,20.889 25.207,20.889 v3(25.705,21.387) ; D2.2@24.8,26.778 25.822,26.778 Bz1.2@27,25.6 27,22.352 v3(27.965,21.387)
NetC3_1: C3.1 D1.2 U1.13 | length 5.3
  Top Layer w0.254: v1(7.163,15.494) 7.18,15.477 8.103,15.477 U1.13@9.836,15.477
  Bottom Layer w0.254: v1(7.163,15.494) 8.407,16.739 D1.2@9.257,16.739
NetC20_2: C20.2 L9.2 L10.1 | length 1.1
  Top Layer w0.146: L9.2@21.046,5.976 21.313,5.976 L10.1@21.562,5.976 ; C20.2@21.301,5.423 21.301,5.963
  Top Layer w0.229: L10.1@21.562,5.976 L10.1@21.574,5.976
NetC25_1: C25.1 U6.F2 | length 2
  Mid Layer 1 w0.2: v4(19.547,6.326) 19.722,6.326 21.006,7.609 v4@21.006,7.62
  other v4: 21.006,7.671
NetC32_1: C32.1 U6.K9 | length 2.2
  Top Layer w0.178: C32.1@15.638,9.155 15.638,9.077 16.104,8.61 16.104,8.606 16.332,8.378 16.336,8.378 16.356,8.358 16.575,8.358 16.83,8.103 17.097,7.836 U6.K9@17.097,7.726
NetC47_2: C47.2 R25.1 U11.F2 | length 2.8
  Bottom Layer w0.203: U11.F2@12.821,37.446 12.821,36.286 C47.2@13.001,36.106
  Bottom Layer w0.381: C47.2@13.001,36.106 13.001,35.836 13.564,35.273 R25.1@13.564,34.917
NetC49_2: C49.2 R31.1 U11.C1 | length 2.5
  Bottom Layer w0.254: U11.C1@13.23,38.647 13.501,38.647 14.022,39.168 C49.2@14.427,39.168
  Bottom Layer w0.381: C49.2@14.659,39.193 14.787,39.065 R31.1@15.705,39.065 R31.1@15.723,39.065
NetCR1_2: CR1.2 F1.4 L15.1 R11.1 | length 2
  Top Layer w0.146: F1.4@23.525,4.625 23.525,3.246 23.565,3.206 L15.1@23.574,3.206 24.096,3.206 cw(c24.096,3.175) R11.1@24.127,3.175
NetD1_1: D1.1 TP1.1 | length 1.3
  Bottom Layer w0.254: TP1.1@10.025,17.975 10.097,17.903 D1.1@10.097,16.739
NetD3_C4: D3.C4 J4.DSW R38.1 | length 9.2
  Mid Layer 2 w0.2: v3(24.486,41.275) 24.968,41.275 26.467,42.774 31.054,42.774 v1(31.569,42.258)
  Bottom Layer w0.2: D3.C4@23.828,40.592 23.878,40.642 R38.1@23.878,41.267 23.886,41.275 v3(24.486,41.275)
NetL2_1: L2.1 U4.12 | length 0.8
  Top Layer w0.254: L2.1@32.296,14.582 32.338,14.582 U4.12@33.113,14.582
NetL11_1: L11.1 L12.2 | length 1.2
  Top Layer w0.2: L12.2@16.749,1.02 16.749,1.973 L11.1@16.849,2.072 16.891,2.114 L11.1@16.891,2.159
NetL11_2: L11.2 U6.A9 | length 1.3
  Top Layer w0.2: L11.2@16.849,3.422 17.097,3.671 U6.A9@17.097,4.576
NetLD1_1: LD1.1 R12.2 | length 2.2
  Bottom Layer w0.146: R12.2@36.048,28.445 36.048,28.46 36.088,28.5 36.103,28.5 36.273,28.67 37.291,28.67 37.725,28.236 LD1.1@37.725,28.025
NetLD1_2: LD1.2 R13.2 | length 0.9
  Bottom Layer w0.203: R13.2@36.048,27.759 36.609,27.759 LD1.2@36.875,28.025
NetLD1_3: LD1.3 R14.2 | length 1
  Bottom Layer w0.203: R14.2@36.048,27.073 36.377,27.073 LD1.3@36.875,26.575
NetLD2_3: LD2.3 R16.2 | length 2.9
  Bottom Layer w0.254: R16.2@34.409,46.101 34.924,46.101 35.797,45.228 LD2.3@36.992,45.228
NetLD2_4: LD2.4 R15.2 | length 2.6
  Bottom Layer w0.254: R15.2@34.409,44.323 36.987,44.323 LD2.4@36.992,44.328
NetLD2_5: LD2.5 R17.2 | length 2.6
  Bottom Layer w0.254: R17.2@34.409,43.434 36.986,43.434 LD2.5@36.992,43.428
NetLD3_3: LD3.3 R19.2 | length 17.9
  Bottom Layer w0.254: R19.2@34.409,46.99 34.976,46.99 36.068,48.082 38.195,48.082 38.331,47.946 38.331,44.3 ccw(c44.3,44.3) 43.263,38.422 ; 43.308,38.406 43.575,38.139 LD3.3@43.575,37
NetLD3_4: LD3.4 R18.2 | length 15.1
  Mid Layer 2 w0.254: v3(35.103,45.212) 37.444,45.212 38.318,44.338 ; 38.331,44.3 ccw(c44.3,44.3) 44.3,38.331 44.375,38.331 44.426,38.28 v3@44.452,38.28
  Bottom Layer w0.254: R18.2@34.409,45.212 v3(35.103,45.212) ; v3@44.452,38.28 44.452,37.023 LD3.4@44.475,37
  other v3: 44.452,38.305
NetLD3_5: LD3.5 R20.2 | length 14.6
  Mid Layer 2 w0.254: v3(35.103,42.545) 38.1,42.545 ; 38.12,42.537 ccw(c44.3,44.3) 44.3,37.874 ; 44.3,37.878 44.962,37.878 v3@45.364,38.28 ; v3@45.326,38.318 v3@45.364,38.356
  Bottom Layer w0.254: R20.2@34.409,42.545 v3(35.103,42.545) ; v3@45.364,38.28 45.364,37.011 LD3.5@45.375,37
  other v3: 45.364,38.305
NetP1_2: P1.2 SB1.1 SB2.1 SB3.2 | length 6.7
  Top Layer w0.508: P1.2@6.579,31.496 7.02,31.937 7.02,34.544
  Bottom Layer w0.508: P1.2@6.579,31.496 P1.2@6.579,32.055 ; P1.2@6.579,31.877 7.442,32.741 SB1.1@9.093,32.741
NetQ1_2: Q1.2 U5.4 | length 5.7
  Bottom Layer w0.125: U5.4@28.876,17.467 32.495,17.467 33.147,16.815 33.553,16.815 33.96,16.408 Q1.2@33.96,16.236
NetQ1_5: Q1.5 Q1.6 R8.2 | length 2.5
  Bottom Layer w0.125: R8.2@32.512,14.955 33.192,14.955 Q1.6@33.31,15.073 ; Q1.6@33.485,15.291 33.485,15.248 Q1.6@33.31,15.073 ; Q1.5@33.96,14.346 Q1.6@33.31,14.346 Q1.6@33.31,15.073
NetQ3_6: Q3.6 R12.1 | length 14.1
  Bottom Layer w0.125: Q3.6@34.214,39.987 34.389,39.812 Q3.6@34.996,39.812 35.219,39.812 35.585,39.446 35.585,36.189 37.377,34.397 37.377,30.543 35.478,28.645 R12.1@35.478,28.445
NetQ4_3: Q4.3 R14.1 | length 27.9
  Mid Layer 2 w0.125: v3(15.125,21.977) 15.284,21.818 18.181,21.818 19.066,22.703 32.681,22.703 35.028,25.05 35.028,26.318 v3(35.154,26.443)
  Bottom Layer w0.125: Q4.3@14.559,22.65 13.858,22.65 Q4.3@13.614,22.893 13.112,22.391 13.112,21.95 13.325,21.737 14.885,21.737 v3(15.125,21.977) ; v3(35.154,26.443) 35.478,26.768 R14.1@35.478,27.073
NetQ4_6: Q4.6 R13.1 | length 29.2
  Mid Layer 2 w0.125: v3(14.021,24.638) 14.021,22.774 14.455,22.34 15.275,22.34 15.547,22.068 18.077,22.068 18.962,22.953 32.577,22.953 34.778,25.153 34.778,26.879 v3(34.976,27.076)
  Bottom Layer w0.125: Q4.6@12.669,24.018 13.439,24.018 Q4.6@13.614,23.843 13.614,24.435 13.818,24.638 v3(14.021,24.638) ; v3(34.976,27.076) 34.976,27.132 35.478,27.634 R13.1@35.478,27.759
NetQ5_1: Q5.1 R21.1 | length 1.3
  Bottom Layer w0.125: R21.1@21.392,20.345 R21.1@21.463,20.345 ; R21.1@21.438,20.371 R21.1@21.463,20.345 ; Q5.1@22.504,19.939 21.869,19.939 R21.1@21.463,20.345
NetQ8_1: Q8.1 R48.1 SW1.4 | length 18.9
  Mid Layer 2 w0.15: v3(4.42,35.433) 4.222,35.433 3.324,34.536 3.324,32.139 4.987,30.477 7.852,30.477 8.357,29.972 10.033,29.972 10.287,29.718 10.287,26.772 v3(10.922,26.137)
  Bottom Layer w0.15: SW1.4@3.875,37.12 3.956,37.039 3.956,35.896 v3(4.42,35.433) ; R48.1@9.754,26.599 10.418,26.599 Q8.1@10.42,26.597 10.88,26.137 v3(10.922,26.137)
NetQ8_3: Q8.3 R47.2 | length 0.6
  Bottom Layer w0.25: Q8.3@11.12,26.822 11.145,26.848 R47.2@11.729,26.848
NetR1_1: R1.1 U1.55 | length 0.9
  Top Layer w0.125: U1.55@25.576,12.977 26.489,12.977 R1.1@26.512,12.954
NetR2_1: R2.1 U1.54 | length 1
  Top Layer w0.125: U1.54@25.576,12.477 26.354,12.477 R2.1@26.512,12.319
NetR3_1: R3.1 U1.53 | length 1.1
  Top Layer w0.125: U1.53@25.576,11.977 26.219,11.977 R3.1@26.512,11.684
NetR7_1: R7.1 U4.3 | length 1.1
  Top Layer w0.125: U4.3@34.663,13.89 v1(35.277,13.89)
  Bottom Layer w0.125: v1(35.277,13.89) 35.277,13.951 35.371,14.045 35.371,14.171 35.443,14.244 R7.1@35.458,14.244
NetR24_1: R24.1 SB1.2 | length 1.4
  Bottom Layer w0.508: R24.1@8.153,34.196 8.73,34.196 9.144,33.782 9.144,33.553
NetR39_1: R39.1 SW2.2 | length 2.4
  Top Layer w0.125: v1(5.359,17.966) 5.359,17.441 SW2.2@5.7,17.1
  Bottom Layer w0.125: R39.1@5.359,16.592 v1(5.359,17.966)
NetR39_2: R39.2 TP28.1 U12.2 | length 24.6
  Top Layer w0.125: TP28.1@4,11 5.075,11 5.598,10.477 6.898,10.477 v1(7.025,10.35)
  Mid Layer 2 w0.125: v6(15.189,10.592) 15.324,10.457 16.556,10.457 16.769,10.67 16.769,10.971 16.558,11.182 v6(16.558,11.227)
  Bottom Layer w0.125: R39.2@5.359,16.022 6.294,15.088 9.931,15.088 10.651,14.368 10.651,10.01 ; v1(7.025,10.35) 9.425,10.35 9.766,10.009 10.651,10.009 14.717,10.009 15.189,10.481 v6(15.189,10.592)
NetSB5_2: SB5.2 U7.9 | length 2
  Bottom Layer w0.125: 30.48,34.602 SB5.2@30.734,34.602 30.833,34.602 31.087,34.602 31.427,34.602 31.953,35.128 U7.9@32.25,35.128
NetSB6_2: SB6.2 U8.9 | length 5.1
  Mid Layer 2 w0.125: v3(26.619,36.881) 28.626,34.874 v3(28.626,34.671)
  Bottom Layer w0.125: U8.9@26.365,38.048 U8.9@26.348,38.065 26.348,37.152 v3(26.619,36.881) ; v3(28.626,34.671) 29.049,34.671 29.268,34.671 SB6.2@29.337,34.602
NetTP5_1: TP5.1 U1.124 | length 1.8
  Top Layer w0.152: U1.124@13.456,20.827 v1(13.9,20.825)
  Bottom Layer w0.152: v1(13.9,20.825) 14.6,20.125 TP5.1@15,20.125
NetTP6_1: TP6.1 U1.125 | length 0.7
  Bottom Layer w0.125: v1(12.956,20.827) 12.956,20.169 TP6.1@13,20.125
NetTP8_1: TP8.1 U6.K6 | length 2.7
  Top Layer w0.125: TP8.1@17.259,10.041 17.496,9.804 17.496,8.689 18.147,8.038 U6.K6@18.147,7.726
nRF52_ANT: L9.1 U6.E1 | length 0.6
  Top Layer w0.146: U6.E1@19.897,5.976 L9.1@20.47,5.976
nRF52_P0.03: TP25.1 U6.A5 | length 9.2
  Top Layer w0.125: U6.A5@18.497,4.576 18.497,4.519 18.825,4.192 v1(18.825,4.145) v1@18.825,4.094
  Mid Layer 2 w0.125: v3(12.5,5.25) 12.722,5.028 17.979,5.028 18.825,4.182 v1(18.825,4.145)
  Bottom Layer w0.125: v3(12.5,5.25) 13.25,4.5 TP25.1@13.25,3.75
nRF52_P0.05: P6.2 U6.D10 | length 6.4
  Top Layer w0.125: v4(16.434,5.74) 16.548,5.626 U6.D10@16.747,5.626
  Mid Layer 1 w0.125: P6.2@11.25,3.75 12.831,5.331 14.454,5.331 14.863,5.74 v4(16.434,5.74)
nRF52_P0.06: P6.1 U6.E9 | length 6.2
  Mid Layer 1 w0.125: P6.1@11.25,5.75 11.419,5.581 14.35,5.581 14.837,6.068 16.563,6.068 16.655,5.976 v4(17.097,5.976)
nRF52_P0.09: C57.2 J5.4 U6.F1 | length 21.7
  Top Layer w0.195: U6.F1@19.897,6.326 20.017,6.326 20.594,6.902 21.552,6.902 21.742,7.092 v1(21.742,7.62)
  Mid Layer 2 w0.19: v3(15.164,16.073) 15.24,15.997 19.003,15.997 21.191,13.809 21.191,10.596 20.923,10.328 20.923,8.44 v1(21.742,7.62)
  Bottom Layer w0.2: J5.4@11.5,13.8 11.5,14.376 11.838,14.714 11.838,15.502 12.333,15.997 15.082,15.997 15.088,16.002 15.093,16.002 v3(15.164,16.073)
nRF52_P0.10: C56.1 J5.2 U6.E2 | length 20.5
  Mid Layer 1 w0.178: v4(19.547,5.976) 19.832,5.976 21.156,7.3 v1(21.3,7.3)
  Mid Layer 2 w0.19: v3(15.164,15.596) 15.24,15.672 18.883,15.672 20.876,13.678 20.876,10.727 20.608,10.458 20.608,7.992 v1(21.3,7.3)
  Bottom Layer w0.2: J5.2@12.5,13.8 12.5,14.376 12.162,14.714 12.162,15.367 12.467,15.672 15.088,15.672 v3(15.164,15.596)
nRF52_P0.11: U1.29 U6.H8 | length 9.5
  Top Layer w0.125: v2(13.157,9.855) 13.157,10.162 13.956,10.961 U1.29@13.956,11.357
  Mid Layer 1 w0.125: v2(13.157,9.855) 12.696,9.394 12.696,7.476 13.354,6.818 15.806,6.818 16.014,7.026 v4(17.447,7.026)
nRF52_P0.14: U6.J7 U12.8 | length 10.9
  Mid Layer 1 w0.125: v1(14.399,14.046) 14.097,13.745 14.097,13.03 14.018,12.952 14.018,10.782 14.742,10.058 16.636,10.058 16.993,9.702 17.246,9.449 17.246,8.486 17.448,8.284 17.579,8.153 17.797,7.935 v4(17.797,7.376)
  Bottom Layer w0.125: v1(14.399,14.046) 14.535,14.046 15.133,13.448 U12.8@15.133,13.071
nRF52_P0.15: U1.30 U6.K7 | length 5.9
  Top Layer w0.125: U1.30@14.456,11.357 14.456,10.344 14.742,10.058 16.295,10.058 17.246,9.107 17.246,8.578 17.797,8.027 U6.K7@17.797,7.726
nRF52_P0.17: R40.1 U6.J6 U12.10 | length 11.6
  Mid Layer 1 w0.125: v1(15.038,14.162) 15.038,13.209 14.268,12.44 14.268,10.894 14.854,10.308 16.74,10.308 17.283,9.765 17.496,9.552 17.496,8.59 18.136,7.95 18.136,7.439 18.11,7.414 v4(18.147,7.376)
  Bottom Layer w0.125: v1(15.038,14.162) 15.853,14.162 16.158,13.857 U12.10@16.158,13.296
nRF52_P0.19: SB10.1 U6.K4 | length 3.9
  Top Layer w0.125: U6.K4@18.847,7.726 18.847,7.921 18.888,7.961 18.888,9.515 19.507,10.135 v1(19.685,10.135)
  Bottom Layer w0.125: v1(19.685,10.135) 19.782,10.135 20.333,10.685 SB10.1@20.521,10.685
nRF52_P0.20: U1.35 U6.J5 | length 4.9
  Mid Layer 1 w0.125: v2(16.956,11.357) 16.956,10.446 17.52,9.882 17.947,9.882 18.388,9.441 18.388,7.578 18.497,7.468 v4(18.497,7.376)
nRF52_P0.21: SB7.1 U6.J4 | length 3.7
  Mid Layer 1 w0.125: v1(18.567,10.262) 18.638,10.191 18.638,7.681 18.847,7.471 v4(18.847,7.376)
  Bottom Layer w0.125: SB7.1@18.235,10.685 18.235,10.431 18.405,10.262 v1(18.567,10.262)
nRF52_P0.22: SB11.1 U6.K3 | length 4.7
  Top Layer w0.125: U6.K3@19.197,7.726 19.138,7.786 19.138,9.376 19.512,9.751 19.881,9.751 20.112,9.982 v1(20.142,9.982)
  Bottom Layer w0.125: v1(20.142,9.982) 20.834,9.982 21.537,10.685 SB11.1@21.664,10.685
nRF52_P0.25: SB9.1 U6.K2 | length 5.6
  Top Layer w0.125: U6.K2@19.547,7.726 19.547,7.953 19.389,8.112 19.389,9.272 19.616,9.5 v1(20.142,9.5)
  Bottom Layer w0.125: v1(20.142,9.5) 21.107,9.5
  Bottom Layer w0.127: 21.107,9.5 21.808,10.2 22.322,10.2 SB9.1@22.807,10.685
nRF52_P0.26: P6.3 U6.C9 | length 13.8
  Mid Layer 1 w0.125: P6.3@9.25,5.75 8.25,4.75 8.25,3.25 9,2.5 11.677,2.5 12.573,3.396 12.573,4.366 13.038,4.831 14.661,4.831 15.006,5.176 16.706,5.176 16.785,5.255 17.076,5.255 v4(17.097,5.276)
nRF52_P0.27: P6.4 U6.D9 | length 10
  Mid Layer 1 w0.125: P6.4@9.25,3.75 10.25,2.75 11.573,2.75 12.323,3.5 12.323,4.469 12.935,5.081 14.557,5.081 14.902,5.426 16.602,5.426 16.778,5.602 17.073,5.602 v4(17.097,5.626)
nRF52_P0.28: P6.5 U6.A6 | length 12.3
  Top Layer w0.125: U6.A6@18.147,4.576 18.147,4.385 18.35,4.182 v1(18.35,4.145)
  Mid Layer 2 w0.125: P6.5@7.25,5.75 8.222,4.778 17.754,4.778 18.35,4.182 v1(18.35,4.145)
nRF52_P0.30: P6.6 U6.A7 | length 12.4
  Top Layer w0.125: U6.A7@17.797,4.576 17.797,4.222 v1(17.875,4.145)
  Mid Layer 2 w0.125: P6.6@7.25,3.75 8.25,2.75 11.573,2.75 13.351,4.528 17.492,4.528 v1(17.875,4.145)
nRF52_P1.00: SB8.1 U6.J3 | length 3.6
  Mid Layer 1 w0.125: v1(19.101,10.262) 18.888,10.048 18.888,7.808 19.197,7.498 v4(19.197,7.376)
  Bottom Layer w0.125: v1@19.099,10.263 19.099,10.406 SB8.1@19.378,10.685
nRF52_P1.01: U1.91 U6.J1 | length 21
  Top Layer w0.125: v1@15.497,20.952 15.956,21.412 U1.91@15.956,21.597 ; U6.J1@19.897,7.376 19.954,7.376 20.185,7.607 20.185,8.017 20.515,8.348 20.515,8.983 20.853,9.322 v1@22.047,9.322
  Mid Layer 2 w0.125: v1(15.506,20.944) 15.706,20.744 15.706,18.199 16.565,17.34 19.063,17.34 22.456,13.947 22.456,10.721 21.705,9.97 21.705,9.558 22.043,9.22 v1(22.073,9.22)
nRF52_P1.04: U1.92 U6.H1 | length 22.1
  Top Layer w0.125: v1@14.997,20.952 15.456,21.412 U1.92@15.456,21.597 ; U6.H1@19.897,7.026 19.957,7.026 20.435,7.503 20.435,7.914 20.649,8.128 20.765,8.244 20.765,8.827 20.991,9.053 21.538,9.053 22.057,8.534 v1@22.073,8.534
  Mid Layer 2 w0.125: v1(15.006,20.944) 15.006,20.931 15.456,20.481 15.456,18.095 16.462,17.09 18.96,17.09 22.206,13.843 22.206,10.825 21.455,10.074 21.455,9.136 22.057,8.534 v1@22.073,8.534
  other v1: 22.073,8.484
nRF52_P1.05: U6.G2 U12.12 | length 12.5
  Mid Layer 1 w0.125: v1(16.739,12.598) 17.207,13.067 20.792,13.067 21.379,12.48 21.379,11.535 21.024,11.18 21.024,8.131 20.134,7.241 20.134,7.168 20.006,7.039 19.743,6.776 19.739,6.776 19.639,6.676 v4(19.547,6.676)
  Bottom Layer w0.125: v1(16.739,12.598) 16.958,12.817 U12.12@16.958,13.296
nRF52_P1.07: U1.93 U6.G1 | length 20.7
  Top Layer w0.125: v1(14.506,20.944) 14.506,20.962 14.956,21.412 U1.93@14.956,21.597 ; U6.G1@19.897,6.676 19.961,6.676 20.685,7.4 20.685,7.81 21.388,8.514 v1(21.388,8.691)
  Mid Layer 2 w0.125: v1(14.506,20.944) 14.506,20.931 15.206,20.231 15.206,17.992 16.358,16.84 18.856,16.84 21.956,13.74 21.956,10.962 21.205,10.211 21.205,8.874 v1(21.388,8.691)
nRF52_P1.08: R23.2 TP10.1 U1.19 U6.G9 U9.3 U10.6 U11.A5 | length 108.8
  Top Layer w0.125: TP10.1@3,34 3.04,33.96 4.478,33.96 ; v2(4.801,26.06) 4.801,26.264 4.247,26.817 4.247,29.001 4.244,29.004 4.244,31.15 4.478,31.384 4.478,33.96 ; v1(8.052,40.792) 8.211,40.633 8.211,40.21 4.478,36.478 4.478,33.96 ; U1.19@9.836,12.477 v8(9.398,12.477) 9.148,12.227 6.322,12.227 4.653,13.896 4.653,21.302 6.047,22.696 6.047,23.486 8.401,25.84 14.291,25.84 v1(14.427,25.977)
  Mid Layer 1 w0.125: v2(4.801,26.06) 5.207,26.06 v2(6.833,24.435) ; v8(9.398,12.477) 9.977,12.477 12.446,10.008 12.446,7.373 13.251,6.568 15.909,6.568 16.017,6.676 v4(17.097,6.676)
  Mid Layer 2 w0.125: 14.229,25.934 14.146,25.85 13.97,25.85 13.776,25.85 ; v3(23.361,32.1) 23.361,30.868 22.69,30.197 20.496,30.197 19.542,29.243 19.542,28.1 18.187,26.745 14.015,26.745 13.633,26.363 13.633,25.993 13.776,25.85 ; v3(38.426,23.55) 38.413,23.55 38.063,23.2 38.063,22.553 37.463,21.953 19.717,21.953 19.082,21.318 14.77,21.318 13.386,22.702 13.386,25.46 13.776,25.85
  Bottom Layer w0.125: v1(8.052,40.792) 8.355,40.489 10.658,40.489 11.127,40.02 11.621,39.527 U11.A5@11.621,39.446 ; R23.2@13.493,25.527 13.806,25.84 14.291,25.84 v1(14.427,25.977) ; v3(23.361,32.1) U9.3@23.9,32.1
nRF52_P1.09: R22.2 TP9.1 U1.20 U6.F10 U9.4 U10.5 U11.A4 | length 110.1
  Top Layer w0.125: v2(4.607,31) 4.497,30.892 4.497,26.923 5.29,26.13 5.29,25.794 5.109,25.613 v2(5.125,25.613) ; v2(4.607,31) 4.728,31.122 4.728,36.374 8.509,40.155 8.509,40.848 8.082,41.275 v1(8.026,41.275) ; U1.20@9.836,11.977 v8(9.398,11.977) 6.219,11.977 4.403,13.793 4.403,21.406 5.797,22.799 5.797,23.911 7.985,26.1 13.882,26.1 v1(13.995,26.213)
  Mid Layer 1 w0.125: v2(3.581,31.013) 4.771,31.013 4.785,31 ; v2(5.125,25.613) 5.301,25.613 6.299,24.615 v2(6.299,24.251) ; v8(9.398,11.977) 10.123,11.977 12.196,9.904 12.196,7.269 13.147,6.318 16.739,6.318 v4(16.747,6.326)
  Mid Layer 2 w0.125: v1(13.995,26.213) 14.122,26.34 14.577,26.34 ; v3(23.361,32.9) 23.784,32.477 23.784,30.937 22.793,29.947 20.599,29.947 19.792,29.14 19.792,27.997 18.291,26.495 14.732,26.495 14.577,26.34 ; v3(38.426,24.05) 38.413,24.05 37.813,23.45 37.813,22.657 37.359,22.203 19.614,22.203 18.979,21.568 14.874,21.568 13.636,22.805 13.636,25.357 13.852,25.573 14.536,25.573 14.79,25.826 14.79,26.127 14.577,26.34
  Bottom Layer w0.125: v1(8.026,41.275) 8.082,41.275 8.618,40.739 10.762,40.739 12.021,39.48 U11.A4@12.021,39.446 ; R22.2@13.493,26.162 13.945,26.162 v1(13.995,26.213) ; v3(23.361,32.9) U9.4@23.9,32.9
nRF52_P1.11: TP26.1 U6.A3 | length 7.2
  Top Layer w0.125: U6.A3@19.197,4.576 19.197,4.289 19.3,4.186 v1@19.3,4.17
  Mid Layer 2 w0.125: v3(13.25,5.75) 13.722,5.278 18.204,5.278 19.3,4.182 v1(19.3,4.145)
nRF52_P1.13: SW4.2 U6.A4 | length 14
  Top Layer w0.15: v1(23.825,7.341) 23.986,7.179 SW4.2@24.623,7.179 ; SW4.2@24.623,10.129 24.681,10.129 25.4,9.41 v1(25.4,9.398)
  Mid Layer 1 w0.15: v4(18.847,4.576) 19.399,4.576 19.886,4.089 v1(20.295,4.089)
  Mid Layer 2 w0.15: v1(20.295,4.089) 21.426,5.221 21.426,6.773 21.72,7.067 ; v1(23.825,7.341) 23.771,7.341 23.498,7.067 21.72,7.067 ; v1(25.4,9.398) 24.051,9.398 21.72,7.067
